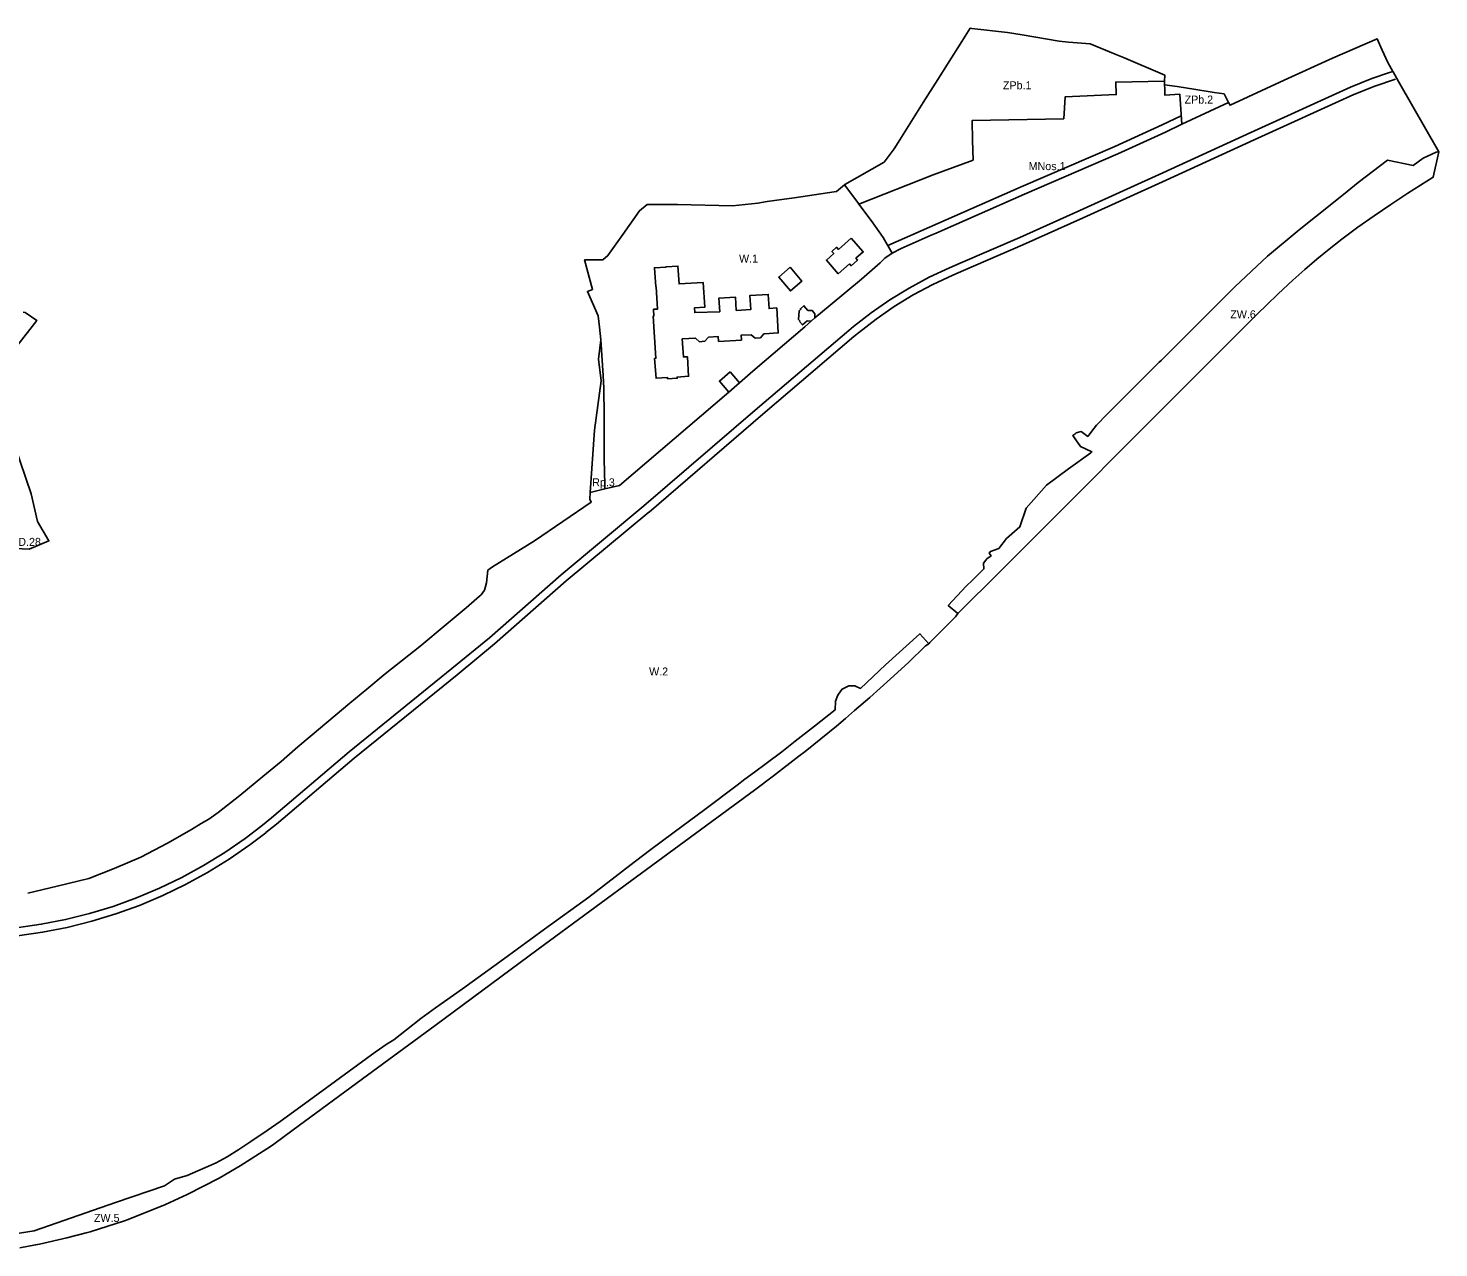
# Model space of a CAD drawing. Extents: x 7414808 to 7417449, y 5544732 to 5546764.
# Drawn here: x 7416568 to 7417449, y 5545193 to 5545955 of the extents above; entities that cross this region are included whole.
import ezdxf

# ---------------------------------------------------------------- set-up
doc = ezdxf.new("R2010")
doc.units = 0
for name, color, linetype in [('LIN_Linie Rozgraniczajace', 7, 'Continuous'), ('LIN_nieprzekraczale linie zabudowy', 7, 'Continuous'), ('LIN_obowiązujące linie zabudowy', 7, 'Continuous'), ('TXT_Oznaczenia Przeznaczenia', 7, 'Continuous')]:
    doc.layers.add(name, color=color, linetype=linetype)

msp = doc.modelspace()

# ---------------------------------------------------------------- linework, layer by layer
at = {"layer": 'LIN_Linie Rozgraniczajace'}
for p, q in [((7417277.74, 5545919.88), (7417277.77, 5545922.08)), ((7417288.59, 5545895.19), (7417317.72, 5545908.85))]:
    msp.add_line(p, q, dxfattribs=at)
for points in [[(7417077.73, 5545857.47), (7417078, 5545857.62), (7417102.53, 5545871.62), (7417108.84, 5545879.89), (7417112.33, 5545885.44), (7417126.96, 5545908.82), (7417136.04, 5545923.24), (7417142.09, 5545932.84), (7417150.97, 5545946.94), (7417156.19, 5545955.2), (7417157.39, 5545955.07), (7417179.52, 5545952.57), (7417188.84, 5545950.98), (7417211.96, 5545947.04), (7417217.76, 5545946.59), (7417231.18, 5545945.53), (7417246.86, 5545939), (7417251.98, 5545936.87), (7417277.83, 5545925.89), (7417277.77, 5545922.08)], [(7417317.72, 5545908.85), (7417318.66, 5545907.08), (7417352.45, 5545922.76), (7417382.71, 5545936.39), (7417410.54, 5545948.67), (7417413.67, 5545941.56), (7417417.13, 5545933.71), (7417420.31, 5545928.15)], [(7416560.54, 5545393.34), (7416575.88, 5545395.51), (7416591.08, 5545398.46), (7416606.12, 5545402.19), (7416620.94, 5545406.7), (7416635.51, 5545411.96), (7416649.78, 5545417.97), (7416663.73, 5545424.71), (7416677.32, 5545432.15), (7416690.5, 5545440.29), (7416703.24, 5545449.1), (7416713.14, 5545456.66), (7416719.79, 5545461.94), (7416768.22, 5545503.15), (7416832.51, 5545555.2), (7416855.92, 5545574.52), (7416900.66, 5545613.85), (7416952.36, 5545656.82), (7417023.41, 5545717.83), (7417080.45, 5545766.4), (7417083.33, 5545768.81), (7417094.48, 5545777.51), (7417106.11, 5545785.56), (7417118.17, 5545792.93), (7417130.63, 5545799.62), (7417143.45, 5545805.59), (7417150.07, 5545808.45), (7417187.25, 5545824.57), (7417224.75, 5545841.29), (7417254.18, 5545854.64), (7417276.63, 5545864.82), (7417331.65, 5545890.09), (7417393.93, 5545918.33), (7417407.29, 5545923.74), (7417417.69, 5545927.26), (7417420.31, 5545928.15)], [(7417086.73, 5545845.37), (7417133.2, 5545863.72), (7417158.13, 5545872.81), (7417157.63, 5545885.11), (7417157.59, 5545897.58), (7417214.71, 5545898.65), (7417215.58, 5545912.27), (7417247.56, 5545913.7), (7417247.21, 5545921.51), (7417277.77, 5545922.08)], [(7417420.31, 5545928.15), (7417420.48, 5545927.86), (7417423.85, 5545921.97), (7417449.04, 5545878.02)], [(7417277.74, 5545919.88), (7417285.49, 5545918.87), (7417297.26, 5545916.98), (7417308.69, 5545915.08), (7417314.87, 5545914.25), (7417317.72, 5545908.85)], [(7417277.74, 5545919.88), (7417277.79, 5545917.44), (7417277.86, 5545913.42), (7417287.16, 5545914.05), (7417288.59, 5545895.19)], [(7417107.56, 5545814.77), (7417113.17, 5545817.68), (7417131.87, 5545825.91), (7417134.99, 5545827.28), (7417138.67, 5545828.9), (7417159.98, 5545838.28), (7417190.15, 5545851.56), (7417248.59, 5545876.75), (7417278.28, 5545890.35), (7417288.59, 5545895.19)], [(7417449.04, 5545878.02), (7417447.48, 5545877.78), (7417439.29, 5545874.01), (7417432.93, 5545869.54), (7417417.09, 5545872.78), (7417398.68, 5545858.76), (7417389.51, 5545851.41), (7417371.96, 5545837.35), (7417361.91, 5545829.24), (7417360.6, 5545828.2), (7417341.96, 5545812.83), (7417321.81, 5545793.78), (7417275.65, 5545747.74), (7417274.33, 5545746.55), (7417258.88, 5545731.1), (7417250.36, 5545722.64), (7417244.56, 5545716.81), (7417241.87, 5545714.11), (7417235.13, 5545707.22), (7417233.65, 5545705.31), (7417229.71, 5545700.23), (7417225.65, 5545703.3), (7417222.59, 5545702.41), (7417221.6, 5545701.62), (7417220.47, 5545700.87), (7417224.21, 5545695.46), (7417224.95, 5545694.42), (7417224.86, 5545694.22), (7417232.34, 5545690.52), (7417231.69, 5545690.04), (7417217.76, 5545679.89), (7417204, 5545669.86), (7417191.18, 5545655.37), (7417187.24, 5545643.74), (7417179.02, 5545636.53), (7417174.14, 5545630.17), (7417168.88, 5545628.4), (7417168.23, 5545627.24), (7417169.29, 5545625.67), (7417166.73, 5545623.7), (7417166.14, 5545623), (7417164.57, 5545621.16), (7417164.87, 5545617.42), (7417157.62, 5545610.4), (7417153.79, 5545606.67), (7417142.56, 5545594.71), (7417148.65, 5545589.58)], [(7417148.65, 5545589.58), (7417175.13, 5545616.08), (7417182.27, 5545623.21), (7417210.57, 5545651.51), (7417267.13, 5545708.04), (7417336.08, 5545777.11), (7417341.42, 5545782.29), (7417348.62, 5545789.32), (7417357.76, 5545797.77), (7417365.29, 5545804.39), (7417372.8, 5545810.93), (7417380.56, 5545817.27), (7417388.39, 5545823.43), (7417398.42, 5545830.93), (7417408.64, 5545838.07), (7417419, 5545845.15), (7417429.74, 5545852.15), (7417445.61, 5545862.14), (7417449.04, 5545878.02)], [(7417077.73, 5545857.47), (7417072.72, 5545853.23), (7417071.36, 5545853.03), (7417067.04, 5545852.38), (7417046.2, 5545849.24), (7417038.53, 5545848.15), (7417029.49, 5545846.87), (7417023.65, 5545846.02), (7417007.85, 5545844.31), (7416973.48, 5545845.14), (7416954.4, 5545845.05), (7416949.58, 5545841.15), (7416939.16, 5545826.27), (7416929.94, 5545813.22), (7416926.8, 5545810.63), (7416915.37, 5545810.58), (7416920.33, 5545791.94), (7416917.14, 5545790.79), (7416923.95, 5545775.47), (7416924.63, 5545768.51), (7416925.45, 5545760.52)], [(7417077.73, 5545857.47), (7417086.07, 5545846.25), (7417086.73, 5545845.37)], [(7417086.73, 5545845.37), (7417094.41, 5545835.04), (7417101.83, 5545824.39), (7417107.56, 5545814.77)], [(7416927.98, 5545667.41), (7416937.26, 5545669.49), (7417005.47, 5545727.9), (7417020.54, 5545740.95), (7417052.89, 5545768.77), (7417059.12, 5545774.23), (7417068.88, 5545782.19), (7417088.34, 5545798.54), (7417099.94, 5545808.68), (7417103.01, 5545811.51), (7417107.56, 5545814.77)], [(7416424.39, 5545654.6), (7416454.9, 5545652.86), (7416463.65, 5545650.29), (7416484.93, 5545644.42), (7416495.09, 5545642.89), (7416503.16, 5545643.72), (7416530.12, 5545636.37), (7416540.79, 5545634.34), (7416542.45, 5545634.25), (7416555.42, 5545630.44), (7416568.36, 5545629.89), (7416580.65, 5545635.01), (7416573.56, 5545647.14), (7416569.62, 5545664.38), (7416559.28, 5545694.98), (7416552.22, 5545718.82), (7416550.7, 5545730.15), (7416554.74, 5545746.53), (7416560.62, 5545756.65), (7416573.12, 5545772.65), (7416565.95, 5545777.69), (7416564.52, 5545777.89)], [(7416918.86, 5545665.15), (7416921.49, 5545704.04), (7416925.76, 5545735.03), (7416924.14, 5545748.53), (7416925.45, 5545760.52)], [(7416925.45, 5545760.52), (7416926.96, 5545738.19), (7416927.49, 5545730.33), (7416927.55, 5545713.18), (7416927.58, 5545685.84), (7416927.92, 5545670.24), (7416927.98, 5545667.41)], [(7416918.86, 5545665.15), (7416927.98, 5545667.41)], [(7416567.53, 5545415.03), (7416585.83, 5545419.31), (7416605.68, 5545424.06), (7416621.43, 5545430.32), (7416638.05, 5545437.52), (7416654.77, 5545446.13), (7416669.83, 5545454.69), (7416675.83, 5545458.37), (7416680.53, 5545461.26), (7416686.53, 5545465.28), (7416700.06, 5545475.91), (7416714.43, 5545487.72), (7416725.78, 5545497.28), (7416734.52, 5545504.83), (7416736.2, 5545506.28), (7416743.97, 5545512.85), (7416745.26, 5545513.93), (7416768.8, 5545533.65), (7416779.29, 5545542.37), (7416790.72, 5545551.85), (7416812.42, 5545568.96), (7416828.78, 5545582.7), (7416841.42, 5545593.26), (7416849.67, 5545600.38), (7416850.7, 5545601.27), (7416852.88, 5545604.29), (7416854.04, 5545608.71), (7416854.83, 5545616.62), (7416857.77, 5545618.87), (7416884.02, 5545634.91), (7416919.5, 5545659.19), (7416918.57, 5545660.94), (7416918.86, 5545665.15)], [(7417130.34, 5545570.78), (7417131.15, 5545571.56), (7417147.12, 5545587.51), (7417148.65, 5545589.58)], [(7416562.54, 5545193.44), (7416572.38, 5545195.24), (7416574.88, 5545195.78), (7416591.9, 5545199.59), (7416604.02, 5545202.76), (7416606.46, 5545203.49), (7416627.86, 5545210.26), (7416630.2, 5545211.15), (7416653.45, 5545220.42), (7416667.07, 5545226.71), (7416687.13, 5545237.01), (7416700.16, 5545244.54), (7416719.07, 5545256.75), (7416721.18, 5545258.18), (7416733.28, 5545267.01), (7416779.67, 5545301.17), (7416821.97, 5545332.33), (7416886.44, 5545379.86), (7416950.93, 5545427.34), (7417021.46, 5545479.25), (7417033.43, 5545488.25), (7417049.3, 5545500.41), (7417053.2, 5545503.53), (7417062.95, 5545511.41), (7417072.65, 5545519.25), (7417078.4, 5545524.08), (7417084.09, 5545528.97), (7417093.54, 5545537.21), (7417106.52, 5545548.9), (7417117.69, 5545559.01), (7417128.44, 5545569.43), (7417130.34, 5545570.78)], [(7417059, 5545519.29), (7417071.85, 5545529.37), (7417072.23, 5545534.82), (7417073.61, 5545538.61), (7417075.49, 5545541.28), (7417076.26, 5545542.37), (7417080.39, 5545544.49), (7417084.11, 5545544.5), (7417087.73, 5545542.88), (7417103.46, 5545557.64), (7417124.83, 5545576.96), (7417130.34, 5545570.78)], [(7416536.88, 5545198.68), (7416571.44, 5545204.08), (7416622.33, 5545221.76), (7416653, 5545232.14), (7416659.25, 5545236.28), (7416666.97, 5545238.62), (7416685.13, 5545246.44), (7416692.08, 5545250.32), (7416699.26, 5545254.75), (7416706.84, 5545259.82), (7416717.11, 5545266.69), (7416725.2, 5545272.38), (7416738.04, 5545281.69), (7416784.57, 5545315.7), (7416792.03, 5545320.75), (7416796.21, 5545323.37), (7416804.17, 5545329.67), (7416813.03, 5545336.7), (7416822.23, 5545343.23), (7416839.13, 5545355.27), (7416864.76, 5545373.72), (7416890.42, 5545392.5), (7416918.06, 5545412.54), (7416943.69, 5545432.32), (7416955.94, 5545441.5), (7416971.39, 5545453.09), (7416990.52, 5545467.17), (7417010.79, 5545482.42), (7417015.51, 5545486.16), (7417021.52, 5545490.46), (7417028.84, 5545495.98), (7417038.53, 5545503.16), (7417047, 5545509.87), (7417059, 5545519.29)]]:
    msp.add_lwpolyline(points, dxfattribs=at)
at = {"layer": 'LIN_nieprzekraczale linie zabudowy'}
for points in [[(7417421.92, 5545923.42), (7417409.04, 5545919.05), (7417395.9, 5545913.73), (7417333.73, 5545885.55), (7417278.7, 5545860.27), (7417226.8, 5545836.73), (7417189.26, 5545819.99), (7417152.06, 5545803.86), (7417145.49, 5545801.02), (7417132.87, 5545795.15), (7417120.66, 5545788.59), (7417108.84, 5545781.36), (7417097.44, 5545773.48), (7417086.47, 5545764.93), (7417083.68, 5545762.59), (7417026.66, 5545714.03), (7416955.64, 5545653.02), (7416955.57, 5545652.97), (7416903.91, 5545610.05), (7416859.16, 5545570.71), (7416835.67, 5545551.33), (7416771.42, 5545499.31), (7416722.96, 5545458.08), (7416716.26, 5545452.74), (7416716.17, 5545452.68), (7416706.18, 5545445.06), (7416693.23, 5545436.11), (7416679.83, 5545427.83), (7416666.02, 5545420.26), (7416651.84, 5545413.41), (7416637.33, 5545407.3), (7416622.52, 5545401.95), (7416607.45, 5545397.37), (7416592.16, 5545393.57), (7416576.7, 5545390.57), (7416561.11, 5545388.37)], [(7417104.78, 5545819.44), (7417188.15, 5545856.14), (7417246.56, 5545881.32), (7417276.18, 5545894.89), (7417288.19, 5545900.52)]]:
    msp.add_lwpolyline(points, dxfattribs=at)
at = {"layer": 'LIN_obowiązujące linie zabudowy'}
for points in [[(7417081.97, 5545824.01), (7417074.05, 5545817.07), (7417072.84, 5545818.43), (7417069.86, 5545815.82), (7417071.06, 5545814.46), (7417066.41, 5545810.39), (7417073.86, 5545801.84), (7417080.86, 5545808.03), (7417081.87, 5545806.86), (7417085.86, 5545810.34), (7417084.87, 5545811.47), (7417089.45, 5545815.46)], [(7417010.12, 5545778.91), (7417009.62, 5545787.25), (7416999.25, 5545786.63), (7416999.79, 5545778.15), (7416984.14, 5545777.58), (7416983.98, 5545780.48), (7416990.4, 5545780.88), (7416989.37, 5545796.47), (7416974.43, 5545795.46), (7416973.68, 5545806.67), (7416966.26, 5545806.16), (7416966.24, 5545806.01), (7416959.01, 5545805.59), (7416959.85, 5545793.73), (7416960.01, 5545793.76), (7416960.93, 5545779.78), (7416958.44, 5545779.66), (7416958.71, 5545775.37), (7416958.31, 5545775.35), (7416959.95, 5545749.01), (7416959.11, 5545748.93), (7416960, 5545736.52), (7416967.19, 5545736.97), (7416967.22, 5545736.21), (7416973.23, 5545736.55), (7416973.2, 5545737.31), (7416980.36, 5545737.77), (7416979.62, 5545750.02), (7416977.08, 5545749.87), (7416976.36, 5545761.17), (7416984.72, 5545761.62), (7416987.26, 5545759.36), (7416990.59, 5545759.65), (7416992.81, 5545762.15), (7416998.83, 5545762.62), (7416999.04, 5545759.6), (7417013.34, 5545760.4), (7417013.1, 5545763.45), (7417019.53, 5545763.78), (7417021.94, 5545761.66), (7417025.25, 5545761.88), (7417027.35, 5545764.25), (7417027.66, 5545764.27), (7417027.72, 5545764.35), (7417036.35, 5545764.84), (7417035.45, 5545780.45), (7417030.62, 5545780.1), (7417030.06, 5545788.92), (7417018.68, 5545788.27), (7417019.16, 5545779.45)], [(7417043.72, 5545805.87), (7417036.62, 5545799.73), (7417043.98, 5545791.15), (7417051.13, 5545797.29)], [(7417054.41, 5545772.35), (7417056.84, 5545772.22), (7417059.12, 5545774.23), (7417059.28, 5545776.73), (7417057.56, 5545778.78), (7417054.87, 5545778.97), (7417052.36, 5545781.81), (7417050.22, 5545779.96), (7417050.49, 5545779.62), (7417049.46, 5545778.74), (7417049.07, 5545773.32), (7417049.96, 5545772.25), (7417049.7, 5545771.99), (7417051.57, 5545769.87)], [(7417006.31, 5545740.5), (7416999.62, 5545734.76), (7417005.47, 5545727.9), (7417012.2, 5545733.6)]]:
    msp.add_lwpolyline(points, close=True, dxfattribs=at)

# ---------------------------------------------------------------- texts
at = {"layer": 'TXT_Oznaczenia Przeznaczenia'}
for s, p in [('ZPb.1', (7417176.72, 5545917.05)), ('ZPb.2', (7417290.2, 5545908.12)), ('MNos.1', (7417192.79, 5545866.55)), ('W.1', (7417011.86, 5545808.84)), ('ZW.6', (7417318.75, 5545773.97)), ('Rp.3', (7416920.12, 5545669.06)), ('KDD.28', (7416552.29, 5545631.86)), ('W.2', (7416955.67, 5545550.9)), ('ZW.5', (7416608.82, 5545209.58))]:
    msp.add_text(s, height=5, dxfattribs=at).set_placement(p)

doc.saveas('drawing.dxf')
